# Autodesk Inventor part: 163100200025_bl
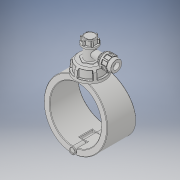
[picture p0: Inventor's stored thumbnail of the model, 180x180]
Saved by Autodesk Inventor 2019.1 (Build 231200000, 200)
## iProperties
Created: 2022-02
Part Number: 163100200025_bl
Material: Generic
Description: Plassadle Tapper 200x32
Document SubType Name: Modeling
Designer: comp2
Density: 1 g/cm^3
Appearance: Default
Author: comp2
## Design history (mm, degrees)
derived "16310.ipt"
feature "Solid1::16310.ipt" dims "ScaleForDerivedMember" = 10
feature "Solid2::16310.ipt" dims "ScaleForDerivedMember" = 10
feature "Solid3::16310.ipt" dims "ScaleForDerivedMember" = 10
feature "Solid4::16310.ipt" dims "ScaleForDerivedMember" = 10
tag "TaggingFeature1"
body "Solid1"
body "Solid2"
body "Solid3"
body "Solid4"
other parameters: "d2" = 246 [user parameter], "d5" = 368 [user parameter], "d7" = 233.7 [user parameter], "d8" = 85 deg [user parameter], "d9" = 45 deg [user parameter], "d10" = 115 [user parameter], "d11" = 49 [user parameter], "d12" = 34.3 [user parameter], "d13" = 40.25 [user parameter], "d14" = 62.1 [user parameter], "d15" = 2.45 [user parameter], "d16" = 2 [user parameter], "d17" = 2 [user parameter], "d18" = 29.4 [user parameter], "d19" = 7.35 [user parameter], "d20" = 1 [user parameter], "d21" = 34.5 [user parameter], "d22" = 1 [user parameter], "d23" = 14.7 [user parameter], "d24" = 103 [user parameter], "d27" = 144 [user parameter], "d29" = 54 [user parameter], "d31" = 43.2 [user parameter], "d32" = 41.2 [user parameter], "d33" = 14.42 [user parameter], "d34" = 93 deg [user parameter], "d35" = 2 [user parameter], "d36" = 4 [user parameter], "d39" = 45 deg [user parameter], "d40" = 4 [user parameter], "d41" = 5 [user parameter], "d42" = 4.6 [user parameter], "d46" = 57.5 [user parameter], "d47" = 27 [user parameter], "d48" = 49 [user parameter], "d49" = 4.92 [user parameter], "d50" = 144 [user parameter], "d51" = 0 [user parameter], "d52" = 32.2 [user parameter], "d53" = 135.3 [user parameter], "d54" = 50.4 [user parameter], "d55" = 0 [user parameter], "d56" = 28.8 [user parameter], "d57" = 28.8 [user parameter], "d59" = 0 [user parameter], "d60" = 144 [user parameter], "d61" = 0 [user parameter], "d62" = 50.4 [user parameter], "d63" = 0 [user parameter], "d65" = 0 [user parameter], "d67" = 0 [user parameter], "d69" = 0 [user parameter], "d70" = 1 [user parameter], "d71" = 138.24 [user parameter], "d72" = 0 [user parameter], "d73" = 2 [user parameter], "d77" = 25 [user parameter], "d78" = 97.75 [user parameter], "d79" = 5.75 [user parameter], "d80" = 60 deg [user parameter], "d81" = 5.75 [user parameter], "d84" = 0 [user parameter], "d85" = 1 [user parameter], "d87" = 360 deg [user parameter], "d90" = 0 [user parameter], "d91" = 1 [user parameter], "d93" = 60 deg [user parameter], "d94" = 3.45 [user parameter], "d95" = 3.45 [user parameter], "d97" = 0 [user parameter], "d98" = 0.5 [user parameter], "d100" = 360 deg [user parameter], "d102" = 2 [user parameter], "d105" = 0 [user parameter], "d106" = 45 deg [user parameter], "d107" = 2.7 [user parameter], "d108" = 2.7 [user parameter], "d109" = 2.95332 [user parameter], "d110" = -8 [user parameter], "d112" = 0 [user parameter], "d113" = 0.5 [user parameter], "d115" = 360 deg [user parameter], "d117" = 0.5 [user parameter], "d1" = 25 [user parameter], "B" = 246 [user parameter], "L" = 144 [user parameter], "E_" = 54 [user parameter], "E1" = 115 [user parameter], "H1" = 368 [user parameter], "H2" = 144 [user parameter], "H3" = 103 [user parameter], "H_costum" = 49 [user parameter]
